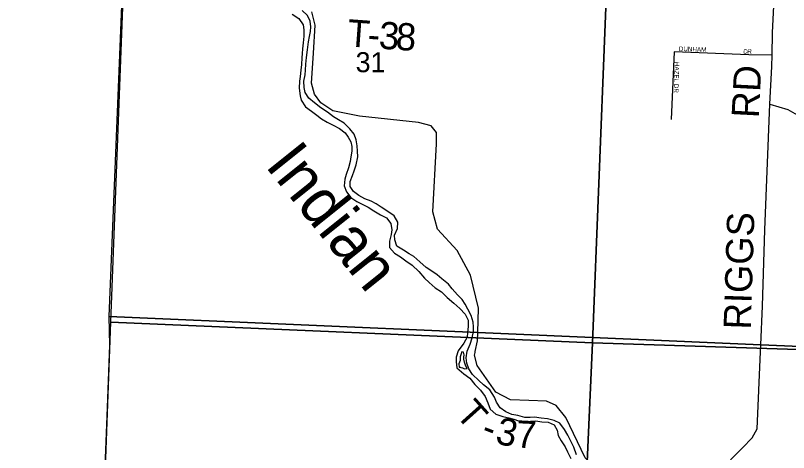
# Model space of a CAD drawing. Extents: x 1310247 to 1552180, y 377264 to 706493.
# Drawn here: x 1313786 to 1322302, y 545763 to 550580 of the extents above; entities that cross this region are included whole.
import ezdxf

# ---------------------------------------------------------------- set-up
doc = ezdxf.new("R2010")
doc.units = 0
for name, color, linetype in [('GM_X_County', 7, 'Continuous'), ('GM_X_County_Road', 7, 'Continuous'), ('GM_X_County_Road_Text', 7, 'Continuous'), ('GM_X_Major_River', 7, 'Continuous'), ('GM_X_Major_River_Text', 7, 'Continuous'), ('GM_X_Section', 7, 'Continuous'), ('GM_X_Section_Text', 7, 'Continuous'), ('GM_X_Township', 7, 'Continuous'), ('GM_X_Township_Road', 7, 'Continuous'), ('GM_X_Township_Road_Text', 7, 'Continuous'), ('GM_X_Township_Subdivision', 7, 'Continuous'), ('GM_X_Township_Subdivision_Text', 7, 'Continuous')]:
    doc.layers.add(name, color=color, linetype=linetype)

msp = doc.modelspace()

# ---------------------------------------------------------------- linework, layer by layer
at = {"layer": 'GM_X_County'}
msp.add_lwpolyline([(1313785.8, 520640.4), (1313963.3, 524640.7), (1314153.8, 529209.1), (1314208.3, 530508.2), (1314346, 533789.5), (1314450.9, 536440.7), (1314451.7, 536483.8), (1314517.5, 538371.8), (1314549.4, 539746.9), (1314757.4, 545143.9), (1314795.6, 546163.4), (1314824.8, 546946.5), (1314816.5, 547262.4), (1315032.4, 552495)], dxfattribs=at)
at = {"layer": 'GM_X_County_Road'}
for points in [[(1321992.4, 546871.5), (1321992.7, 546878.6), (1321995.6, 546951.1), (1322013.3, 547376.5), (1322040.5, 548216.4), (1322096.4, 549601.3), (1322115.9, 550019.4), (1322122.3, 550144.2), (1322125.3, 550387.2), (1322134.3, 550613.9), (1322189.1, 551564.5), (1322259.9, 553458.3)], [(1322096.4, 549601.3), (1322294.8, 549543.1), (1322525.5, 549411.9), (1322670, 549349.5), (1323313, 549125.9), (1323842.5, 548931.7), (1324390.2, 548741), (1324629.9, 548641.7), (1324858.8, 548584.8), (1325200.3, 548474.4), (1325281.8, 548446.6), (1325748.4, 548265.1), (1326187.6, 548062.2), (1326910.4, 547727.8)], [(1314209.5, 530536.6), (1314346, 533789.5), (1314450.9, 536440.7), (1314451.7, 536483.8), (1314517.5, 538371.8), (1314549.4, 539746.9), (1314757.4, 545143.9), (1314795.6, 546163.4), (1314824.8, 546946.5)], [(1321250.9, 545135.2), (1321272.1, 545177.7), (1321329.7, 545322.4), (1321362.4, 545360.2), (1321400.2, 545402.3), (1321537.6, 545553.1), (1321794.3, 545816.1), (1321902.2, 545923.9), (1321957.3, 546025.1), (1321992.4, 546871.5)]]:
    msp.add_lwpolyline(points, dxfattribs=at)
at = {"layer": 'GM_X_Major_River'}
for points in [[(1316834, 550596.3), (1316908.9, 550546.3), (1316953.3, 550477), (1316963.9, 550420.6), (1316962.1, 550352.4), (1316956.2, 550278.4), (1316948.5, 550212.3), (1316945.2, 550162.3), (1316939.9, 550112.2), (1316936, 550040.1), (1316930.4, 549976.1), (1316922.6, 549908.1), (1316915.3, 549856.1), (1316909.3, 549780), (1316921.2, 549695.4), (1316933.9, 549645), (1316980.2, 549573.6), (1317045.2, 549525.9), (1317104.2, 549480.3), (1317155.3, 549440.9), (1317218.5, 549403.3)], [(1317288.2, 549463.8), (1317221.3, 549513.5), (1317148.3, 549561.5), (1317081.6, 549617.3), (1317016.7, 549667), (1316976.2, 549730.2), (1316965.6, 549784.6), (1316963.4, 549854.9), (1316977.2, 549926.8), (1316980.6, 549978.8), (1316984.3, 550045), (1316990.2, 550117), (1317002.4, 550203), (1317014.7, 550291), (1317024.2, 550348.9), (1317035.6, 550404.8), (1317040.9, 550454.8), (1317032.6, 550519.2), (1317004, 550580.1), (1316943.3, 550633.8)], [(1319967.8, 545738.7), (1319937.8, 545821.7), (1319909.1, 545874.6), (1319869.1, 545955.8), (1319834.5, 546016.8), (1319784.2, 546086.3), (1319720.8, 546117.9), (1319645.1, 546133.8), (1319575.1, 546141.6), (1319505.1, 546151.3), (1319454.9, 546148.5), (1319396.8, 546150), (1319319.2, 546171.9), (1319253.3, 546183.6), (1319187.9, 546211.3), (1319126.8, 546254.9), (1319086.4, 546320.1), (1319061.7, 546372.9), (1319011.6, 546452.4), (1318942.9, 546510.2), (1318891.9, 546555.6), (1318819.5, 546623.6), (1318778.9, 546684.8), (1318758.5, 546749.5), (1318750, 546805.8), (1318761.9, 546881.8), (1318793.9, 546957.2), (1318817.8, 547026.9), (1318829.6, 547096.8), (1318830.9, 547148.9), (1318828.2, 547199.1), (1318806.1, 547273.9), (1318769.7, 547343), (1318741.1, 547399.9), (1318706.3, 547450.9), (1318655.5, 547500.3), (1318597.1, 547567.9), (1318554.3, 547619.1), (1318483.6, 547679.1), (1318432.5, 547720.4), (1318361.6, 547770.3), (1318310.3, 547801.7), (1318241.8, 547865.5), (1318173.1, 547923.4), (1318121.7, 547954.8), (1318060.5, 547992.4), (1317987.5, 548036.3), (1317963.3, 548109.1), (1317962.6, 548159.3), (1317994.5, 548230.7), (1317996.3, 548300.9), (1317956, 548372.1), (1317887, 548417.9), (1317814, 548465.8), (1317758.9, 548505.3), (1317703.4, 548532.8), (1317635.9, 548558.5), (1317566.7, 548596.3), (1317507.7, 548641.9), (1317473.1, 548696.9), (1317474.4, 548749), (1317498.2, 548816.7), (1317517.6, 548868.3), (1317539.3, 548934), (1317555.6, 549021.9), (1317555.2, 549086.1), (1317550.7, 549144.4), (1317538.3, 549208.9), (1317515.9, 549273.6), (1317469.3, 549330.9), (1317406.7, 549392.7), (1317343.5, 549430.3), (1317288.2, 549463.8)], [(1317218.5, 549403.3), (1317285.8, 549371.5), (1317355.1, 549335.7), (1317416, 549288.1), (1317450.8, 549237.1), (1317479.6, 549186.2), (1317492.3, 549135.8), (1317491, 549083.6), (1317481.4, 549021.7), (1317472, 548969.8), (1317454.3, 548902), (1317428.3, 548828.4), (1317415, 548776.6), (1317407, 548702.5), (1317433.4, 548637.7), (1317479.9, 548574.4), (1317545, 548530.6), (1317606.4, 548501), (1317669.7, 548467.4), (1317734.8, 548427.7), (1317807.9, 548383.8), (1317871.2, 548350.1), (1317919.7, 548286.7), (1317930, 548218.3), (1317922.6, 548166.3), (1317904.7, 548092.5), (1317907, 548024.2), (1317961.5, 547960.7), (1318026.6, 547919), (1318087.7, 547877.4), (1318154.6, 547829.6), (1318231, 547757.5), (1318293.3, 547685.7), (1318344.2, 547638.3), (1318408.9, 547578.6), (1318477.9, 547532.8), (1318542.4, 547471), (1318615.1, 547411), (1318681.7, 547351.2), (1318740.3, 547289.6), (1318772.6, 547220.6), (1318772.9, 547152.3), (1318767.1, 547084.3), (1318761.8, 547034.3), (1318726, 546966.9), (1318663.7, 546884.2), (1318639.9, 546814.6), (1318640.6, 546762.4), (1318648.9, 546696), (1318723.4, 546632), (1318790.3, 546582.2), (1318846.7, 546512.6), (1318909.2, 546448.8), (1318961.6, 546379.3), (1318989.9, 546310.4), (1319014.2, 546241.6), (1319076.9, 546185.9), (1319154.5, 546162), (1319220.3, 546146.3), (1319274, 546130.9), (1319325.7, 546111.6), (1319387.6, 546104.1), (1319458, 546110.4), (1319518.2, 546112.9), (1319584.1, 546101.2), (1319654.2, 546099.5), (1319719.6, 546069.8), (1319752.1, 546008.8), (1319764.7, 545950.4), (1319795.3, 545893.4), (1319839.7, 545826.1), (1319868.3, 545771.3), (1319904.5, 545696.2)], [(1318719.5, 546868.8), (1318701.5, 546871.2), (1318694.9, 546849.3), (1318686.1, 546817.5), (1318683.1, 546777.4), (1318670.1, 546739.6), (1318673.2, 546705.4)], [(1318673.2, 546705.4), (1318683.2, 546703.2), (1318691.1, 546701), (1318711.1, 546696.5), (1318730.8, 546685.9), (1318761, 546689.2), (1318747.6, 546715.6), (1318741.9, 546727.8), (1318730.7, 546760.2), (1318725.5, 546792.4), (1318726.1, 546812.5), (1318726.8, 546840.5), (1318719.5, 546868.8)]]:
    msp.add_lwpolyline(points, dxfattribs=at)
at = {"layer": 'GM_X_Section'}
for points in [[(1315039.8, 552503.3), (1320349.9, 552243.3), (1320142.5, 546971.1), (1314837.1, 547199.2)], [(1320349.9, 552243.3), (1325704.6, 552080.5), (1325455.2, 546798.8), (1320142.5, 546971.1)], [(1320142.5, 546971.1), (1319907.5, 541709.9), (1314641.9, 541886.8), (1314837.1, 547199.2)], [(1325455.2, 546798.8), (1325267.1, 541570.4), (1319907.5, 541709.9), (1320142.5, 546971.1)]]:
    msp.add_lwpolyline(points, close=True, dxfattribs=at)
at = {"layer": 'GM_X_Township'}
for points in [[(1329978.5, 546605), (1325109.8, 546816.1), (1321995.7, 546951.1), (1318877.6, 547086.3), (1314816.5, 547262.4), (1315032.4, 552495)], [(1313785.8, 520640.4), (1313963.3, 524640.7), (1314153.8, 529209.1), (1314208.3, 530508.2), (1314346, 533789.5), (1314450.9, 536440.7), (1314451.7, 536483.8), (1314517.5, 538371.8), (1314549.4, 539746.9), (1314757.4, 545143.9), (1314795.6, 546163.4), (1314824.8, 546946.5), (1314816.5, 547262.4), (1318877.6, 547086.3), (1321995.7, 546951.1), (1325109.8, 546816.1), (1329978.5, 546605)]]:
    msp.add_lwpolyline(points, dxfattribs=at)
at = {"layer": 'GM_X_Township_Road'}
for points in [[(1318848.8, 546866.3), (1318850.8, 546876.4), (1318874.8, 546994.8), (1318877.6, 547086.3), (1318886.1, 547355.6), (1318797.2, 547718.9), (1318651.8, 547991.3), (1318433.1, 548225.5), (1318383.9, 548417.2), (1318425.3, 549166.4), (1318422.5, 549288.8), (1318366.3, 549364.4), (1318226.8, 549402), (1317574.4, 549470.6), (1317283, 549530.1), (1317148.7, 549615.7), (1317079, 549711.8), (1317046.1, 549834.9), (1317070.7, 550165.3), (1317086.7, 550473.7), (1317052.3, 550619)], [(1320993.3, 545589.3), (1320857.8, 545512.2), (1320689.7, 545426.1), (1320634.8, 545390.8), (1320535.6, 545346.3), (1320429.4, 545383.6), (1320366.2, 545424), (1320063.3, 545703.2), (1319847.6, 546148), (1319740.8, 546281.7), (1319633.9, 546330.5), (1319440, 546336.7), (1319239.8, 546345), (1319076.8, 546430.1), (1318871.7, 546724.1), (1318842.5, 546835.2), (1318848.8, 546866.3)]]:
    msp.add_lwpolyline(points, dxfattribs=at)
at = {"layer": 'GM_X_Township_Subdivision'}
for points in [[(1321040.2, 550180.5), (1321007.3, 549434)], [(1322122.3, 550144.2), (1321865.3, 550147.6), (1321040.2, 550180.5)]]:
    msp.add_lwpolyline(points, dxfattribs=at)

# ---------------------------------------------------------------- texts
at = {"layer": 'GM_X_County_Road_Text'}
for s, rotation, p in [('RD', 87.04403, (1321973.3, 549445.4)), ('RIGGS', 88.17443, (1321885.4, 547116.1))]:
    msp.add_text(s, height=300, rotation=rotation, dxfattribs=at).set_placement(p)
at = {"layer": 'GM_X_Major_River_Text'}
msp.add_text('Indian', height=499.89, rotation=308.67099, dxfattribs=at).set_placement((1316526.5, 548924.4))
at = {"layer": 'GM_X_Section_Text'}
msp.add_text('31', height=221, rotation=0.00001, dxfattribs=at).set_placement((1317532.9, 549954.7))
at = {"layer": 'GM_X_Township_Road_Text'}
for s, rotation, p in [('T', 355.93812, (1317434.5, 550240.2)), ('3', 356.02138, (1317781.7, 550215.6)), ('8', 356.42032, (1317968.3, 550202.6)), ('-', 355.96095, (1317658.4, 550224.3)), ('T', 311.86828, (1318621.9, 546178.4)), ('3', 347.72898, (1319060.8, 545865.8)), ('7', 357.04954, (1319294, 545819.5)), ('-', 338.9621, (1318897.9, 545924.3))]:
    msp.add_text(s, height=300, rotation=rotation, dxfattribs=at).set_placement(p)
at = {"layer": 'GM_X_Township_Subdivision_Text'}
for s, rotation, p in [('DUNHAM', 358.1827, (1321092.8, 550188.2)), ('D', 356.41318, (1321801.6, 550161.8)), ('R', 357.81783, (1321846.8, 550159)), ('HAZEL DR', 268.31516, (1321048.5, 550068.5))]:
    msp.add_text(s, height=50, rotation=rotation, dxfattribs=at).set_placement(p)

doc.saveas('drawing.dxf')
